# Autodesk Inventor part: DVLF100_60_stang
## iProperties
Created: 2010-03
Part Number: DVLF100_60_stang
Document SubType Name: Modeling
Designer: TB
Mass: 918.695 g
Surface Area: 680.695 cm^2
Volume: 918.695 cm^3
Density: 1 g/cm^3
Author: TB
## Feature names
1. Revolution1
2. Fillet1
3. Revolution2
